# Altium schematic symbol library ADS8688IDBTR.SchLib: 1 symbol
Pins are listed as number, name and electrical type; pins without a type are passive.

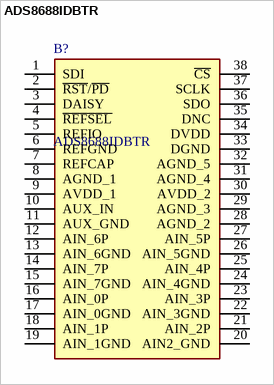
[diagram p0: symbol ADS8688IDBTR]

## ADS8688IDBTR
designator B?
Octal Channel Single ADC SAR 500ksps 16-bit Serial 38-Pin TSSOP T/R; Manufacturer_Name: Texas Instruments; Geometry.Height: 1.2mm
footprint SOP50P640X120-38N
pins: 1 SDI, 2 ~{RST}/~{PD}, 3 DAISY, 4 ~{REFSEL}, 5 REFIO, 6 REFGND, 7 REFCAP, 8 AGND_1, 9 AVDD_1, 10 AUX_IN, 11 AUX_GND, 12 AIN_6P, 13 AIN_6GND, 14 AIN_7P, 15 AIN_7GND, 16 AIN_0P, 17 AIN_0GND, 18 AIN_1P, 19 AIN_1GND, 20 AIN2_GND, 21 AIN_2P, 22 AIN_3GND, 23 AIN_3P, 24 AIN_4GND, 25 AIN_4P, 26 AIN_5GND, 27 AIN_5P, 28 AGND_2, 29 AGND_3, 30 AVDD_2, 31 AGND_4, 32 AGND_5, 33 DGND, 34 DVDD, 35 DNC, 36 SDO, 37 SCLK, 38 ~{CS}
